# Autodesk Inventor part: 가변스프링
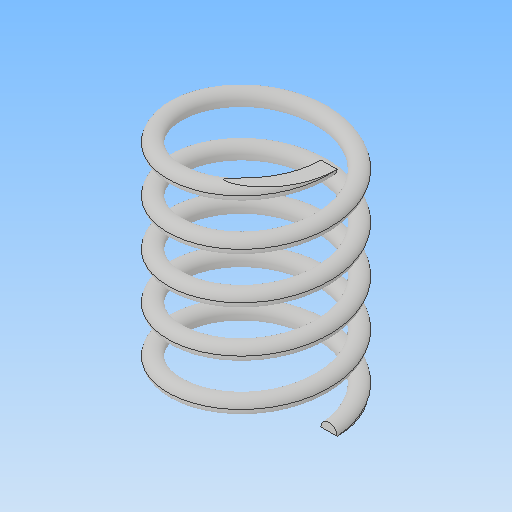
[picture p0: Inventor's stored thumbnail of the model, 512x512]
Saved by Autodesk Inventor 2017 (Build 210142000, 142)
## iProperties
Part Number: 가변스프링
Material: 일반
Document SubType Name: Modeling
Designer: MRC
Density: 1 g/cm^3
Appearance: 기본값
Mass: 0.874626 g
Surface Area: 17.7559 cm^2
Volume: 0.874626 cm^3
Author: MRC
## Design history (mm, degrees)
sketch "스케치1"
  geometry: L1 (0, 0)-(0, 28.5); L2 (0, 28.5)-(9, 28.5); L3 (0, 0)-(9, 0); C1 r 1 at (9, 0)
  constraints: 6 end point, 2 horizontal, 1 centre point, 1 coincident, 1 vertical
  dimensions: "d0" = 28.5 distance of L1.start L1.end (derived); "d1" = 9 distance of L1.end L2.end; "d2" = 9 distance of L1.start L3.end; "d3" = 2 diameter of C1
feature "코일1" sketch "스케치1" pitch "d4" = 10; turns "d6" = 5; dims "d5" = 28.5 (= d0), "d7" = 0, angle "d8" = 90 deg, angle "d9" = 90 deg, "d10" = 0, "d11" = 0
sketch "스케치2"
  geometry: L1 (28.5, 12.5)-(0, 12.5); L2 (0, 12.5)-(0, -12.5); L3 (0, -12.5)-(28.5, -12.5); L4 (28.5, -12.5)-(28.5, 12.5); 2 further points
  constraints: 8 end point, 2 parallel, 1 coincident, 1 horizontal, 1 midpoint, 1 perpendicular
  dimensions: "d12" = 28.5 distance of L2.end L3.end (= d0); "d13" = 25 distance of L3.end L1.start
extrude "돌출1" sketch "스케치2" stored distance "d14" = 0; taper "d15" = 0 deg
node "솔리드1"
